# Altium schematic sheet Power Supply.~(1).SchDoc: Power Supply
size 431 x 279 mm; Date: Not shown in title block; ApprovedBy: Not shown in title block; CheckedBy: Not shown in title block; Author: Not shown in title block; CompanyName: Not shown in title block; Engineer: Not shown in title block; Organization: Not shown in title block; Address1: Not shown in title block; Address2: Not shown in title block; Address3: Not shown in title block; Address4: Not shown in title block; DocumentNumber: 3; Revision: Use project parameter SCH_Rev; SheetNumber: 3; SheetTotal: 9; PageSetup: Record=PageOptions|CenterHorizontal=True|CenterVertical=True|PrintScale=1.00|XCorrection=1.00|YCorrection=1.00|PrintKind=0|BorderSize=5000000|LeftOffset=0|BottomOffset=0|Orientation=2|PaperLength=1000|PaperWidth=1000|Scale=100|PaperSource=15|PrintQuality=600|MediaType=1|DitherType=10|PaperKind=Letter|PrintScaleMode=1
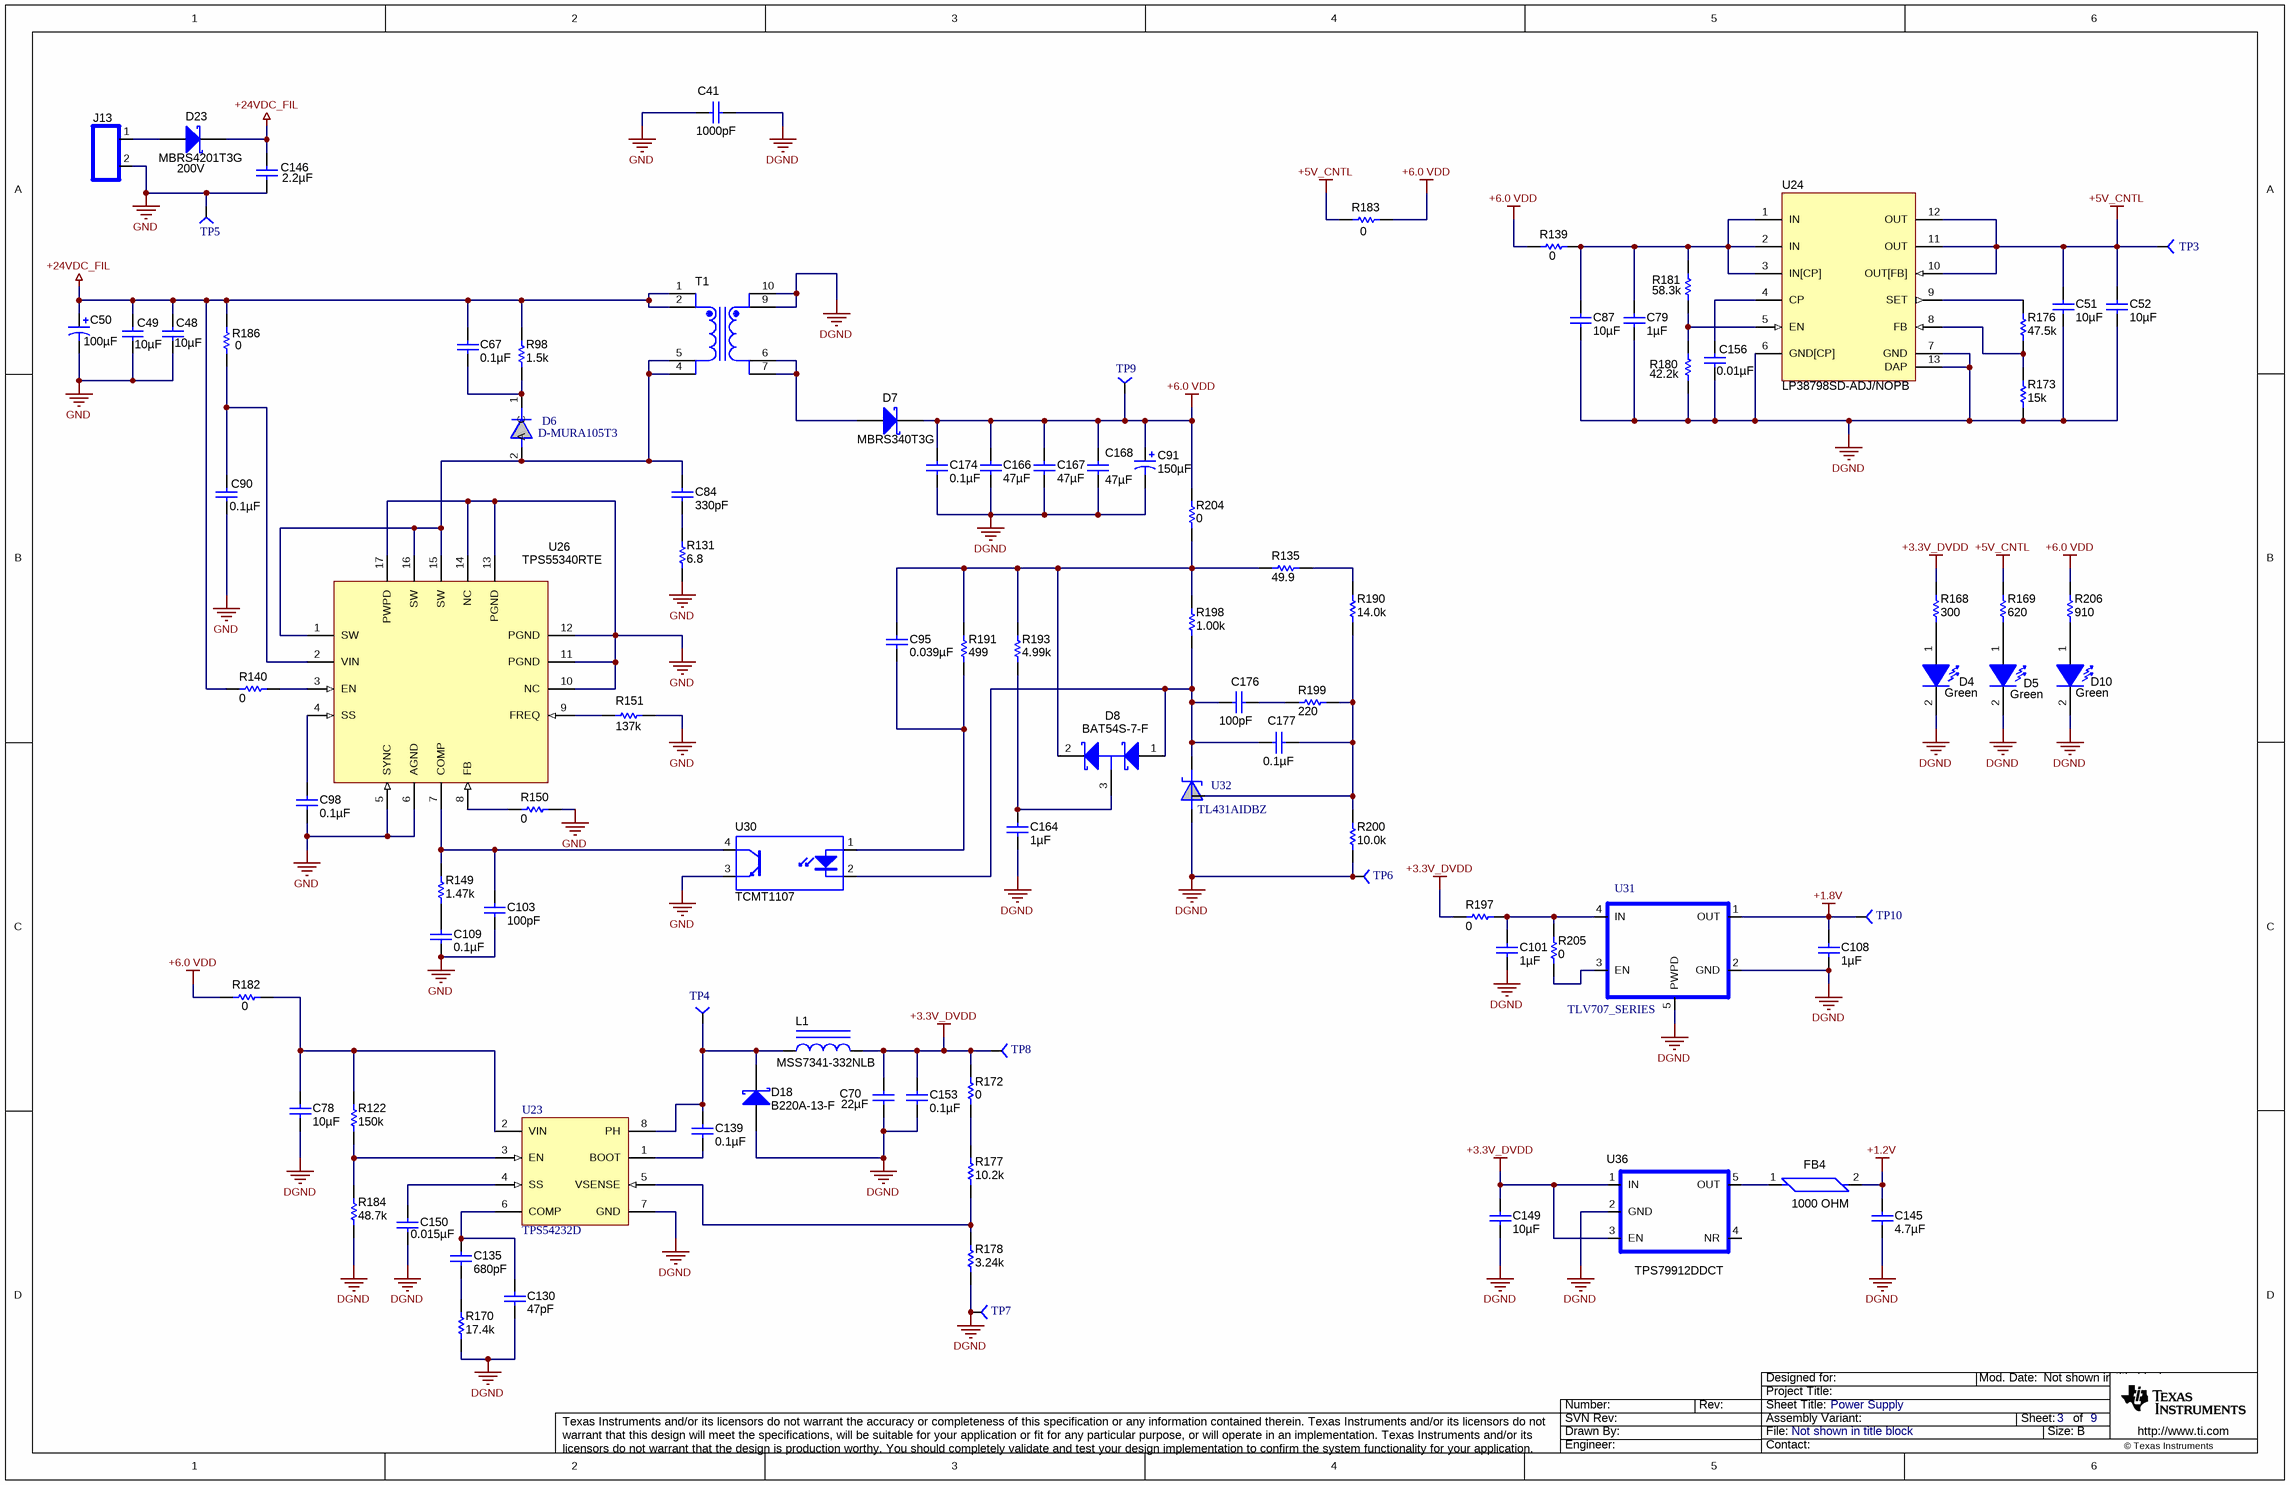
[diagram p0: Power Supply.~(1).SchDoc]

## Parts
C41  value 1000pF  [1206]
C48  ValueDisplayed: 10µF  [1210]  (hidden comment: GRM32ER71H106KA12L)
C49  ValueDisplayed: 10µF  [1210]  (hidden comment: GRM32ER71H106KA12L)
C50  ValueDisplayed: 100µF  [HE_800x1150]  (hidden comment: UHE1H101MPD)
C51  ValueDisplayed: 10µF  [1206]  (hidden comment: GRM31CR71C106KAC7L)
C52  ValueDisplayed: 10µF  [1206]  (hidden comment: GRM31CR71C106KAC7L)
C67  ValueDisplayed: 0.1µF  [0603]  (hidden comment: C0603C104K5RACTU)
C70  ValueDisplayed: 22µF  [1210]  (hidden comment: C3225X5R1A226M)
C78  ValueDisplayed: 10µF  [1206]  (hidden comment: GMK316AB7106KL)
C79  ValueDisplayed: 1µF  [1206]  (hidden comment: 12063C105KAT2A)
C84  ValueDisplayed: 330pF  [0603]  (hidden comment: 06035A331JAT2A)
C87  ValueDisplayed: 10µF  [1206]  (hidden comment: GRM31CR71C106KAC7L)
C90  ValueDisplayed: 0.1µF  [0603]  (hidden comment: C0603C104K5RACTU)
C91  ValueDisplayed: 150µF  [SM_RADIAL_6.3BMM]  (hidden comment: UUD1C151MCL1GS)
C95  ValueDisplayed: 0.039µF  [0603]  (hidden comment: GRM188R71H393KA61D)
C98  ValueDisplayed: 0.1µF  [0603]  (hidden comment: 06035C104KAT2A)
C101  ValueDisplayed: 1µF  [0603]  (hidden comment: GRM188R71A105KA61D)
C103  ValueDisplayed: 100pF  [0603]  (hidden comment: C1608C0G1H101J)
C108  ValueDisplayed: 1µF  [0603]  (hidden comment: GRM188R71A105KA61D)
C109  ValueDisplayed: 0.1µF  [0603]  (hidden comment: C0603C104K5RACTU)
C130  ValueDisplayed: 47pF  [0402]  (hidden comment: GRM1555C1E470JA01D)
C135  ValueDisplayed: 680pF  [0603]  (hidden comment: GRM1885C1E681JA01D)
C139  ValueDisplayed: 0.1µF  [0603]  (hidden comment: 0603YC104JAT2A)
C145  ValueDisplayed: 4.7µF  [0603]  (hidden comment: C0603C475K9PACTU)
C146  ValueDisplayed: 2.2µF  [1210]
C149  ValueDisplayed: 10µF  [1210]
C150  ValueDisplayed: 0.015µF  [0603]  (hidden comment: GRM188R71C153KA01D)
C153  ValueDisplayed: 0.1µF  [0603]  (hidden comment: C0603X104K8RACTU)
C156  ValueDisplayed: 0.01µF  [0805_HV]  (hidden comment: 08055C103KAT2A)
C164  ValueDisplayed: 1µF  [0603]  (hidden comment: C0603C105K4PACTU)
C166  ValueDisplayed: 47µF  [1210]  (hidden comment: GRM32ER61A476KE20L)
C167  ValueDisplayed: 47µF  [1210]  (hidden comment: GRM32ER61A476KE20L)
C168  ValueDisplayed: 47µF  [1210]  (hidden comment: GRM32ER61A476KE20L)
C174  ValueDisplayed: 0.1µF  [0603]  (hidden comment: C0603X104K8RACTU)
C176  ValueDisplayed: 100pF  [0603]  (hidden comment: C1608C0G1H101J)
C177  ValueDisplayed: 0.1µF  [0603]  (hidden comment: C0603C104K5RACTU)
D4  value Green  [LED_0603]  (hidden comment: LG L29K-G2J1-24-Z)
D5  value Green  [LED_0603]  (hidden comment: LG L29K-G2J1-24-Z)
D6  D-MURA105T3  [403D]
D7  MBRS340T3G  [SMC]
D8  BAT54S-7-F  [SOT-23]
D10  value Green  [LED_0603]  (hidden comment: LG L29K-G2J1-24-Z)
D18  B220A-13-F  [SMA]
D23  value 200V  [SMC]  (hidden comment: MBRS4201T3G)
FB4  value 1000 OHM  [FB0603]
J13  TBLK_15A_2X5.1MM  [TB_2X5.1MM]  (value not drawn)
L1  MSS7341-332NLB  [MSS7341]
R98  value 1.5k  [1206]  (hidden comment: CRCW12061K50JNEA)
R122  value 150k  [0603]  (hidden comment: RC0603FR-07150KL)
R131  value 6.8  [1206]  (hidden comment: CRCW12066R80JNEA)
R135  value 49.9  [0603]  (hidden comment: CRCW060349R9FKEA)
R139  value 0  [0603]  (hidden comment: CRCW06030000Z0EA)
R140  value 0  [0603]  (hidden comment: CRCW06030000Z0EA)
R149  value 1.47k  [0603]  (hidden comment: RC0603FR-071K47L)
R150  value 0  [0603]  (hidden comment: CRCW06030000Z0EA)
R151  value 137k  [0603]  (hidden comment: CRCW0603137KFKEA)
R168  value 300  [0603]  (hidden comment: CRCW0603300RJNEA)
R169  value 620  [0603]  (hidden comment: RC0603FR-07620RL)
R170  value 17.4k  [0603]  (hidden comment: CRCW060317K4FKEA)
R172  value 0  [0603]  (hidden comment: RC0603JR-070RL)
R173  value 15k  [0603]  (hidden comment: CRCW060315K0JNEA)
R176  value 47.5k  [0603]  (hidden comment: CRCW060347K5FKEA)
R177  value 10.2k  [0603]  (hidden comment: CRCW060310K2FKEA)
R178  value 3.24k  [0603]  (hidden comment: CRCW06033K24FKEA)
R180  value 42.2k  [0603]  (hidden comment: RC0603FR-0742K2L)
R181  value 58.3k  [0603]  (hidden comment: RT0603BRD0758K3L)
R182  value 0  [1206]  (hidden comment: CRCW12060000Z0EA)
R183  value 0  [1206]  (hidden comment: CRCW12060000Z0EA)
R184  value 48.7k  [0603]  (hidden comment: CRCW060348K7FKEA)
R186  value 0  [0603]  (hidden comment: CRCW06030000Z0EA)
R190  value 14.0k  [0603]  (hidden comment: CRCW060314K0FKEA)
R191  value 499  [0603]  (hidden comment: CRCW0603499RFKEA)
R193  value 4.99k  [0603]  (hidden comment: CRCW06034K99FKEA)
R197  value 0  [0603]  (hidden comment: RC0603JR-070RL)
R198  value 1.00k  [0603]  (hidden comment: CRCW06031K00FKEA)
R199  value 220  [0603]  (hidden comment: RC0603FR-07220RL)
R200  value 10.0k  [0603]  (hidden comment: CRCW060310K0FKEA)
R204  value 0  [0603]  (hidden comment: CRCW06030000Z0EA)
R205  value 0  [0603]  (hidden comment: RC0603JR-070RL)
R206  value 910  [0603]  (hidden comment: RG1608P-911-B-T5)
T1  (no value)  [XFARMER]
TP3  TP-SMALL  [TP-SMALL]  (value not drawn)
TP4  TP-SMALL  [TP-SMALL]  (value not drawn)
TP5  TP-SMALL  [TP-SMALL]  (value not drawn)
TP6  TP-SMALL  [TP-SMALL]  (value not drawn)
TP7  TP-SMALL  [TP-SMALL]  (value not drawn)
TP8  TP-SMALL  [TP-SMALL]  (value not drawn)
TP9  TP-SMALL  [TP-SMALL]  (value not drawn)
TP10  TP-SMALL  [TP-SMALL]  (value not drawn)
U23  TPS54232D  [D0008A_N]
U24  LP38798SD-ADJ/NOPB  [DNT0012B]
U26  TPS55340RTE  [RTE0016C]
U30  TCMT1107  [SOP-4]
U31  TLV707_SERIES  [UDFN-4P-1X1_MM]
U32  TL431AIDBZ  [SOT-23]
U36  TPS79912DDCT  [DDC0005A_N]

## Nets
+1.2V: C145.1 FB4.2
+1.8V: C108.1 TP10.1 U31.1(OUT)
+3.3V_DVDD: C70.1 C149.1 C153.1 L1.2 R168.2 R172.2 R197.2 TP8.1 U36.1(IN) U36.3(EN)
+5V_CNTL: C51.1 C52.1 R169.2 R183.1 TP3.1 U24.10(OUT[FB]) U24.11(OUT) U24.12(OUT)
+6.0 VDD: C91.1(+) C166.1 C167.1 C168.1 C174.1 D7.1(K) R139.2 R182.1 R183.2 R204.2 R206.2 TP9.1
+24VDC_FIL: C48.1 C49.1 C50.1(+) C67.1 C146.1 D23.1(K) R98.2 R140.2 R186.2 T1.1 T1.2
DGND: C41.2 C51.2 C52.2 C70.2 C78.2 C79.2 C87.2 C91.2(-) C101.2 C108.2 C130.2 C145.2 C149.2 C150.2 C153.2 C156.2 C164.2 C166.2 C167.2 C168.2 C174.2 D4.2(K) D5.2(K) D10.2(K) D18.2(A) R170.1 R173.1 R178.1 R180.1 R184.1 R200.1 T1.9 T1.10 TP6.1 TP7.1 U23.7(GND) U24.6(GND[CP]) U24.7(GND) U24.13(DAP) U31.2(GND) U31.5(PWPD) U32.3(A) U36.2(GND)
GND: C41.1 C48.2 C49.2 C50.2(-) C90.2 C98.2 C103.2 C109.2 C146.2 J13.2 R131.1 R150.2 R151.2 TP5.1 U26.5(SYNC) U26.6(AGND) U26.10(NC) U26.11(PGND) U26.12(PGND) U26.13(PGND) U26.14(NC) U26.17(PWPD) U30.3(E)
NetC67_2: C67.2 D6.1(C) R98.1
NetC78_1: C78.1 R122.2 R182.2 U23.2(VIN)
NetC79_1: C79.1 C87.1 R139.1 R181.2 U24.1(IN) U24.2(IN) U24.3(IN[CP])
NetC84_1: C84.1 D6.2(A) T1.4 T1.5 U26.1(SW) U26.15(SW) U26.16(SW)
NetC84_2: C84.2 R131.2
NetC90_1: C90.1 R186.1 U26.2(VIN)
NetC95_1: C95.1 D8.2(K) R135.1 R191.2 R193.2 R198.2 R204.1
NetC95_2: C95.2 R191.1 U30.1(A)
NetC98_1: C98.1 U26.4(SS)
NetC101_1: C101.1 R197.1 R205.2 U31.4(IN)
NetC103_1: C103.1 R149.2 U26.7(COMP) U30.4(C)
NetC109_1: C109.1 R149.1
NetC130_1: C130.1 C135.1 U23.6(COMP)
NetC135_2: C135.2 R170.2
NetC139_1: C139.1 D18.1(K) L1.1 TP4.1 U23.8(PH)
NetC139_2: C139.2 U23.1(BOOT)
NetC150_1: C150.1 U23.4(SS)
NetC156_1: C156.1 U24.4(CP)
NetC164_1: C164.1 D8.3(C) R193.1
NetC176_1: C176.1 R199.1
NetC176_2: C176.2 C177.1 D8.1(A) R198.1 U30.2(K) U32.1(C)
NetC177_2: C177.2 R190.1 R199.2 R200.2 U32.2(REF)
NetD4_1: D4.1(A) R168.1
NetD5_1: D5.1(A) R169.1
NetD7_2: D7.2(A) T1.6 T1.7
NetD10_1: D10.1(A) R206.1
NetD23_2: D23.2(A) J13.1
NetFB4_1: FB4.1 U36.5(OUT)
NetR122_1: R122.1 R184.2 U23.3(EN)
NetR135_2: R135.2 R190.2
NetR140_1: R140.1 U26.3(EN)
NetR150_1: R150.1 U26.8(FB)
NetR151_1: R151.1 U26.9(FREQ)
NetR172_1: R172.1 R177.2
NetR173_2: R173.2 R176.1 U24.8(FB)
NetR176_2: R176.2 U24.9(SET)
NetR177_1: R177.1 R178.2 U23.5(VSENSE)
NetR180_2: R180.2 R181.1 U24.5(EN)
NetR205_1: R205.1 U31.3(EN)

Not connected (* = marked no-connect by the designer): U36 4(NR)

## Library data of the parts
C41 = 202R18W102KV4E: CAP, CERM, 1000pF, 2KV 10% X7R 1206; Manufacturer: Johanson Dielectrics Inc; Polarized: N; CompType: Capacitor; Cap_F: 0.000000001; Tolerance_%: 0
C48 C49 = GRM32ER71H106KA12L: CAP, CERM, 10uF, 50V, +/-10%, X7R, 1210; Manufacturer: MuRata; Polarized: N; CompType: Capacitor; U/M: EA; Cap_F: 0.00001; Tolerance_%: 10; Value1: Unknown; VDC_V: 50; TaMin_C: -55; TaMax_C: 125
C50 = UHE1H101MPD: CAP, AL, 100uF, 50V, +/-20%, 0.17 ohm, TH; Manufacturer: Nichicon; Polarized: Y; CompType: Capacitor; U/M: EA; Cap_F: 0.0001; Tolerance_%: 20; VDC_V: 50; ESR_Ohm: 0.17; IRMS_A: 0.555; TaMin_C: -40; TaMax_C: 105; Cap_Case: 8x11.5
C51 C52 C87 = GRM31CR71C106KAC7L: CAP, CERM, 10uF, 16V, +/-10%, X7R, 1206; Manufacturer: MuRata; Polarized: N; CompType: Capacitor; U/M: EA; Cap_F: 0.00001; Tolerance_%: 10; Value1: Unknown; VDC_V: 16; TaMin_C: -55; TaMax_C: 125
C67 C90 C109 C177 = C0603C104K5RACTU: CAP, CERM, 0.1uF, 50V, +/-10%, X7R, 0603; Manufacturer: Kemet; Polarized: N; CompType: Capacitor; U/M: EA; Cap_F: 0.0000001; Tolerance_%: 10; Value1: Unknown; VDC_V: 50; TaMin_C: -55; TaMax_C: 125
C70 = C3225X5R1A226M: CAP, CERM, 22uF, 10V, +/-20%, X5R, 1210; Manufacturer: TDK; Polarized: N; CompType: Capacitor; U/M: EA; Cap_F: 0.000022; Tolerance_%: 20; ESR_Ohm: 0.002; Value1: 0.002 ohm; VDC_V: 10; IRMS_A: 3.2; TaMin_C: -55; TaMax_C: 85
C78 = GMK316AB7106KL: CAP, CERM, 10uF, 35V, +/-10%, X7R, 1206; Manufacturer: Taiyo Yuden; Polarized: N; CompType: Capacitor; U/M: EA; Cap_F: 0.00001; Tolerance_%: 10; Value1: Unknown; VDC_V: 35; TaMin_C: -55; TaMax_C: 125
C79 = 12063C105KAT2A: CAP, CERM, 1uF, 25V, +/-10%, X7R, 1206; Manufacturer: AVX; Polarized: N; CompType: Capacitor; U/M: EA; Cap_F: 0.000001; Tolerance_%: 10; ESR_Ohm: 0.013; Value1: 0.013 ohm; VDC_V: 25; TaMin_C: -55; TaMax_C: 125
C84 = 06035A331JAT2A: CAP, CERM, 330pF, 50V, +/-5%, C0G/NP0, 0603; Manufacturer: AVX; Polarized: N; CompType: Capacitor; U/M: EA; Cap_F: 0.00000000033; Tolerance_%: 5; ESR_Ohm: 0.071; Value1: 0.071 ohm; VDC_V: 50; TaMin_C: -55; TaMax_C: 125
C91 = UUD1C151MCL1GS: CAP, AL, 150uF, 16V, +/-20%, 0.34 ohm, SMD; Manufacturer: Nichicon; Polarized: Y; CompType: Capacitor; U/M: EA; Cap_F: 0.00015; Tolerance_%: 20; VDC_V: 16; ESR_Ohm: 0.34; IRMS_A: 0.28; TaMin_C: -55; TaMax_C: 105; Cap_Case: 6.3x7.7
C95 = GRM188R71H393KA61D: CAP, CERM, 0.039uF, 50V, +/-10%, X7R, 0603; Manufacturer: MuRata; Polarized: N; CompType: Capacitor; U/M: EA; Cap_F: 0.000000039; Tolerance_%: 10; Value1: Unknown; VDC_V: 50; TaMin_C: -55; TaMax_C: 125
C98 = 06035C104KAT2A: CAP, CERM, 0.1uF, 50V, +/-10%, X7R, 0603; Manufacturer: AVX; Polarized: N; CompType: Capacitor; U/M: EA; Cap_F: 0.0000001; Tolerance_%: 10; Value1: Unknown; VDC_V: 50; TaMin_C: -55; TaMax_C: 125
C101 C108 = GRM188R71A105KA61D: CAP, CERM, 1uF, 10V, +/-10%, X7R, 0603; Manufacturer: MuRata; Polarized: N; CompType: Capacitor; U/M: EA; Cap_F: 0.000001; Tolerance_%: 10; ESR_Ohm: 0.011; Value1: 0.011 ohm; TaMin_C: -55; TaMax_C: 125
C103 C176 = C1608C0G1H101J: CAP, CERM, 100pF, 50V, +/-5%, C0G/NP0, 0603; Manufacturer: TDK; Polarized: N; CompType: Capacitor; U/M: EA; Cap_F: 0.0000000001; Tolerance_%: 5; ESR_Ohm: 0.1679; Value1: 0.1679 ohm; VDC_V: 50; TaMin_C: -55; TaMax_C: 125
C130 = GRM1555C1E470JA01D: CAP, CERM, 47pF, 25V, +/-5%, C0G/NP0, 0402; Manufacturer: MuRata; Polarized: N; CompType: Capacitor; U/M: EA; Cap_F: 0.000000000047; Tolerance_%: 5; Value1: Unknown; VDC_V: 25; TaMin_C: -55; TaMax_C: 125
C135 = GRM1885C1E681JA01D: CAP, CERM, 680pF, 25V, +/-5%, C0G/NP0, 0603; Manufacturer: MuRata; Polarized: N; CompType: Capacitor; U/M: EA; Cap_F: 0.00000000068; Tolerance_%: 5; Value1: Unknown; VDC_V: 25; TaMin_C: -55; TaMax_C: 125
C139 = 0603YC104JAT2A: CAP, CERM, 0.1uF, 16V, +/-5%, X7R, 0603; Manufacturer: AVX; Polarized: N; CompType: Capacitor; U/M: EA; Cap_F: 0.0000001; Tolerance_%: 5; ESR_Ohm: 0.039; Value1: 0.039 ohm; VDC_V: 16; TaMin_C: -55; TaMax_C: 125
C145 = C0603C475K9PACTU: CAP, CERM, 4.7uF, 6.3V, +/-10%, X5R, 0603; Manufacturer: Kemet; Polarized: N; CompType: Capacitor; U/M: EA; Cap_F: 0.0000047; Tolerance_%: 10; ESR_Ohm: 0.006; Value1: 0.006 ohm; VDC_V: 6.3; IRMS_A: 7.24; TaMin_C: -55; TaMax_C: 85
C146 = GRM32ER72A225KA35L: CAP, CERM, 2.2uF, 100V, +/-10%, X7R, 1210; Manufacturer: MuRata; Polarized: N; CompType: Capacitor; U/M: EA; Cap_F: 0.0000022; Tolerance_%: 10; ESR_Ohm: 0.007; Value1: 0.007 ohm; VDC_V: 100; IRMS_A: 4.4; TaMin_C: -55; TaMax_C: 125
C149 = GMK325AB7106MM-T: CAP, CERM, 10uF, 35V, +/-20%, X7R, 1210; Manufacturer: Taiyo Yuden; Polarized: N; CompType: Capacitor; U/M: EA; Cap_F: 0.00001; Tolerance_%: 20; Value1: Unknown; VDC_V: 35; TaMin_C: -55; TaMax_C: 125
C150 = GRM188R71C153KA01D: CAP, CERM, 0.015uF, 16V, +/-10%, X7R, 0603; Manufacturer: MuRata; Polarized: N; CompType: Capacitor; U/M: EA; Cap_F: 0.000000015; Tolerance_%: 10; Value1: Unknown; VDC_V: 16; TaMin_C: -55; TaMax_C: 125
C153 C174 = C0603X104K8RACTU: CAP, CERM, 0.1uF, 10V, +/-10%, X7R, 0603; Manufacturer: Kemet; Polarized: N; CompType: Capacitor; U/M: EA; Cap_F: 0.0000001; Tolerance_%: 10; Value1: Unknown; TaMin_C: -55; TaMax_C: 125
C156 = 08055C103KAT2A: CAP, CERM, 0.01uF, 50V, +/-10%, X7R, 0805; Manufacturer: AVX; Polarized: N; CompType: Capacitor; U/M: EA; Cap_F: 0.00000001; Tolerance_%: 10; ESR_Ohm: 0.078; Value1: 0.078 ohm; VDC_V: 50; TaMin_C: -55; TaMax_C: 125; Cap_Case: 0805
C164 = C0603C105K4PACTU: CAP, CERM, 1uF, 16V, +/-10%, X5R, 0603; Manufacturer: Kemet; Polarized: N; CompType: Capacitor; U/M: EA; Cap_F: 0.000001; Tolerance_%: 10; Value1: Unknown; VDC_V: 16; TaMin_C: -55; TaMax_C: 85
C166-C168 = GRM32ER61A476KE20L: CAP, CERM, 47uF, 10V, +/-10%, X5R, 1210; Manufacturer: MuRata; Polarized: N; CompType: Capacitor; U/M: EA; Cap_F: 0.000047; Tolerance_%: 10; ESR_Ohm: 0.001; Value1: 0.001 ohm; TaMin_C: -55; TaMax_C: 85
D4 D5 D10 = LG M47K-G1J2-24-Z: LED SMARTLED GREEN 570NM 0603; Manufacturer: OSRAM Opto Semiconductors Inc; Vf_V: 1.7V; Io_A: 0.002; RJC_CperW: 530; Tjmax_C: 100; Value1: W; U/M: EA
D6 = D-MURA105T3: Rectifier, Ultrafast Power, 50V 1A; Manufacturer: On Semi; Area: 4088
D7 = MBRS340T3G: Diode, Schottky, 40V, 3A, SMC; Manufacturer: ON Semiconductor; U/M: EA; Vf_V: 0.525; Value2: 0.525V; Io_A: 3; Vr_V: 40; TJmax_C: 125; RJC_CperW: 11
D8 = BAT54S-7-F: Diode, Schottky, 30V, 0.2A, SOT-23; Manufacturer: Diodes Inc.; U/M: EA; Vf_V: 0.65; Value2: 0.65V; Io_A: 0.2; Vr_V: 30; TJmax_C: 125
D18 = B220A-13-F: Diode, Schottky, 20V, 2A, SMA; Manufacturer: Diodes Inc.; U/M: EA; Vf_V: 0.5; Value2: 0.5V; Io_A: 2; Vr_V: 20; TJmax_C: 150
D23 = MBRS4201T3G: Diode, Schottky, 200V, 4A, SMC; Manufacturer: ON Semiconductor; Io_A: 4
FB4 = MMZ1608B102C: FERRITE CHIP 1000 OHM 300MA 0603; Manufacturer: TDK Corporation; CompType: Ferrite Bead
J13 = TBLK_15A_2X5.1MM: Terminal Block, 2-pin, 15-A, 5.1mm; Manufacturer: OST; PartNumber: ED120/2DS; area: 141600; Value: ED120/2DS
L1 = MSS7341-332NLB: Inductor, Shielded Drum Core, Ferrite, 3.3uH, 3.72A, 0.02 ohm, SMD; Manufacturer: Coilcraft; Ind_H: 3.3E-6; ValueDisplayed: 3.3µH; Imax_A: 3.72; Irms: 5A @ 40C rise; Isat: 3.72A @ 30% inductance drop; DCR_ohm: 0.02; U/M: EA
R98 = CRCW12061K50JNEA: RES, 1.5k ohm, 5%, 0.25W, 1206; Manufacturer: Vishay-Dale; CompType: Resistor; Res_ohm: 1500; Value_Code: 1k50; Tolerance_%: 5; Power_W: 0.25; VDC_V: 200; TempCo: 200 ppm/C; EIA_Code: E24; U/M: EA
R122 = RC0603FR-07150KL: RES, 150k ohm, 1%, 0.1W, 0603; Manufacturer: Yageo America; CompType: Resistor; Res_ohm: 150000; Tolerance_%: 1; Power_W: 0.1; VDC_V: 150; TempCo: 200 ppm/C; EIA_Code: E96; U/M: EA
R131 = CRCW12066R80JNEA: RES, 6.8 ohm, 5%, 0.25W, 1206; Manufacturer: Vishay-Dale; CompType: Resistor; Value_Code: 6R80; Tolerance_%: 5; Power_W: 0.25; VDC_V: 200; TempCo: 200 ppm/C; EIA_Code: E24; U/M: EA
R135 = CRCW060349R9FKEA: RES, 49.9 ohm, 1%, 0.1W, 0603; Manufacturer: Vishay-Dale; CompType: Resistor; Value_Code: 49R9; Tolerance_%: 1; Power_W: 0.1; VDC_V: 75; TempCo: 100 ppm/C; EIA_Code: E96; U/M: EA
R139 R140 R150 R186 R204 = CRCW06030000Z0EA: RES, 0 ohm, 5%, 0.1W, 0603; Manufacturer: Vishay-Dale; CompType: Resistor; Value_Code: 0000; Tolerance_%: 5; Power_W: 0.1; VDC_V: 75; TempCo: 200 ppm/C; EIA_Code: E24; U/M: EA
R149 = RC0603FR-071K47L: RES, 1.47k ohm, 1%, 0.1W, 0603; Manufacturer: Yageo America; CompType: Resistor; Res_ohm: 1470; Value_Code: 1k47; Tolerance_%: 1; Power_W: 0.1; VDC_V: 150; TempCo: 200 ppm/C; EIA_Code: E96; U/M: EA
R151 = CRCW0603137KFKEA: RES, 137k ohm, 1%, 0.1W, 0603; Manufacturer: Vishay-Dale; CompType: Resistor; Res_ohm: 137000; Tolerance_%: 1; Power_W: 0.1; VDC_V: 75; TempCo: 100 ppm/C; EIA_Code: E96; U/M: EA
R168 = CRCW0603300RJNEA: RES, 300 ohm, 5%, 0.1W, 0603; Manufacturer: Vishay-Dale; CompType: Resistor; Value_Code: 300R; Tolerance_%: 5; Power_W: 0.1; VDC_V: 75; TempCo: 200 ppm/C; EIA_Code: E24; U/M: EA
R169 = RC0603FR-07620RL: RES, 620 ohm, 1%, 0.1W, 0603; Manufacturer: Yageo America; CompType: Resistor; Value_Code: 620R; Tolerance_%: 1; Power_W: 0.1; VDC_V: 150; TempCo: 200 ppm/C; U/M: EA
R170 = CRCW060317K4FKEA: RES, 17.4k ohm, 1%, 0.1W, 0603; Manufacturer: Vishay-Dale; CompType: Resistor; Res_ohm: 17400; Value_Code: 17k4; Tolerance_%: 1; Power_W: 0.1; VDC_V: 75; TempCo: 100 ppm/C; EIA_Code: E96; U/M: EA
R172 R197 R205 = RC0603JR-070RL: RES, 0 ohm, 5%, 0.1W, 0603; Manufacturer: Yageo America; CompType: Resistor; Value_Code: 0000; Tolerance_%: 5; Power_W: 0.1; VDC_V: 50; TempCo: 200 ppm/C; EIA_Code: E24; U/M: EA
R173 = CRCW060315K0JNEA: RES, 15k ohm, 5%, 0.1W, 0603; Manufacturer: Vishay-Dale; CompType: Resistor; Res_ohm: 15000; Value_Code: 15k0; Tolerance_%: 5; Power_W: 0.1; VDC_V: 75; TempCo: 200 ppm/C; EIA_Code: E24; U/M: EA
R176 = CRCW060347K5FKEA: RES, 47.5k ohm, 1%, 0.1W, 0603; Manufacturer: Vishay-Dale; CompType: Resistor; Res_ohm: 47500; Value_Code: 47k5; Tolerance_%: 1; Power_W: 0.1; VDC_V: 75; TempCo: 100 ppm/C; EIA_Code: E96; U/M: EA
R177 = CRCW060310K2FKEA: RES, 10.2k ohm, 1%, 0.1W, 0603; Manufacturer: Vishay-Dale; CompType: Resistor; Res_ohm: 10200; Value_Code: 10k2; Tolerance_%: 1; Power_W: 0.1; VDC_V: 75; TempCo: 100 ppm/C; EIA_Code: E96; U/M: EA
R178 = CRCW06033K24FKEA: RES, 3.24k ohm, 1%, 0.1W, 0603; Manufacturer: Vishay-Dale; CompType: Resistor; Res_ohm: 3240; Value_Code: 3k24; Tolerance_%: 1; Power_W: 0.1; VDC_V: 75; TempCo: 100 ppm/C; EIA_Code: E96; U/M: EA
R180 = RC0603FR-0742K2L: RES, 42.2k ohm, 1%, 0.1W, 0603; Manufacturer: Yageo America; CompType: Resistor; Res_ohm: 42200; Value_Code: 42k2; Tolerance_%: 1; Power_W: 0.1; VDC_V: 150; TempCo: 200 ppm/C; EIA_Code: E96; U/M: EA
R181 = RT0603BRD0758K3L: RES, 58.3k ohm, 0.1%, 0.1W, 0603; Manufacturer: Yageo America; CompType: Resistor; Res_ohm: 58300; Value_Code: 58k3; Tolerance_%: 0.1; VDC_V: 75; TempCo: 25 ppm/C; EIA_Code: E192; U/M: EA
R182 R183 = CRCW12060000Z0EA: RES, 0 ohm, 5%, 0.25W, 1206; Manufacturer: Vishay-Dale; CompType: Resistor; Value_Code: 0000; Tolerance_%: 5; Power_W: 0.25; VDC_V: 200; TempCo: 200 ppm/C; EIA_Code: E24; U/M: EA
R184 = CRCW060348K7FKEA: RES, 48.7k ohm, 1%, 0.1W, 0603; Manufacturer: Vishay-Dale; CompType: Resistor; Res_ohm: 48700; Value_Code: 48k7; Tolerance_%: 1; Power_W: 0.1; VDC_V: 75; TempCo: 100 ppm/C; EIA_Code: E96; U/M: EA
R190 = CRCW060314K0FKEA: RES, 14.0k ohm, 1%, 0.1W, 0603; Manufacturer: Vishay-Dale; CompType: Resistor; Res_ohm: 14000; Value_Code: 14k0; Tolerance_%: 1; Power_W: 0.1; VDC_V: 75; TempCo: 100 ppm/C; EIA_Code: E96; U/M: EA
R191 = CRCW0603499RFKEA: RES, 499 ohm, 1%, 0.1W, 0603; Manufacturer: Vishay-Dale; CompType: Resistor; Value_Code: 499R; Tolerance_%: 1; Power_W: 0.1; VDC_V: 75; TempCo: 100 ppm/C; EIA_Code: E96; U/M: EA
R193 = CRCW06034K99FKEA: RES, 4.99k ohm, 1%, 0.1W, 0603; Manufacturer: Vishay-Dale; CompType: Resistor; Res_ohm: 4990; Value_Code: 4k99; Tolerance_%: 1; Power_W: 0.1; VDC_V: 75; TempCo: 100 ppm/C; EIA_Code: E96; U/M: EA
R198 = CRCW06031K00FKEA: RES, 1.00k ohm, 1%, 0.1W, 0603; Manufacturer: Vishay-Dale; CompType: Resistor; Res_ohm: 1000; Value_Code: 1k00; Tolerance_%: 1; Power_W: 0.1; VDC_V: 75; TempCo: 100 ppm/C; EIA_Code: E96; U/M: EA
R199 = RC0603FR-07220RL: RES, 220 ohm, 1%, 0.1W, 0603; Manufacturer: Yageo America; CompType: Resistor; Value_Code: 220R; Tolerance_%: 1; Power_W: 0.1; VDC_V: 150; TempCo: 200 ppm/C; U/M: EA
R200 = CRCW060310K0FKEA: RES, 10.0k ohm, 1%, 0.1W, 0603; Manufacturer: Vishay-Dale; CompType: Resistor; Res_ohm: 10000; Value_Code: 10k0; Tolerance_%: 1; Power_W: 0.1; VDC_V: 75; TempCo: 100 ppm/C; EIA_Code: E96; U/M: EA
R206 = RG1608P-911-B-T5: RES, 910 ohm, 0.1%, 0.1W, 0603; Manufacturer: Susumu Co Ltd; CompType: Resistor; Value_Code: 910R; Tolerance_%: 0.1; VDC_V: 75; TempCo: 25 ppm/C; U/M: EA
T1 = Transformer: SymbolCreator: a0411947; DCR_Ohm: 0.11; Value: 12uH; LeakageL: 0.130uH; U/M: EA
TP3-TP10 = TP-SMALL: Test Point, 0.020 Hole; Manufacturer: STD; Value: STD
U23 = TPS54232D: Buck Step Down Regulator with 3.5 to 28 V Input and 0.8 to 25 V Output, -40 to 150 degC, 8-Pin SOIC (D), Green (RoHS & no Sb/Br); Manufacturer: Texas Instruments; Alternate Manufacturer: None; Alternate PartNumber: Equivalent; Duty Cycle(Max)(%): 90; Iout(Max)(A): 2; Iq(Typ)(mA): 0.11; Rating: Catalog; Regulated Outputs(#): 1; SubFamily: Step-Down Regulator; Switch Current Limit(Typ)(A): 2.3; Vin(Max)(V): 28; Vin(Min)(V): 3.5; Vout(Max)(V): 25; Vout(Min)(V): 0.8
U24 = LP38798SD-ADJ/NOPB: Ultra Low Noise, 800 mA Linear Voltage Regulator for RF/Analog Circuits, DNT0012B; Alternate Manufacturer: None; Manufacturer: Texas Instruments; SymbolCreator: a0799628; CompType: IC; U/M: EA
U26 = TPS55340RTE: Integrated 5-A 40-V Wide Input Range Boost/SEPIC/Flyback DC-DC Regulator, RTE0016C; Alternate Manufacturer: None; Manufacturer: Texas Instruments; SymbolCreator: a0412235; CompType: IC; U/M: EA
U30 = TCMT1107: Optocoupler, 3.75kV RMS, SMT; Manufacturer: Vishay-Semiconductor; U/M: EA
U31 = TLV707_SERIES: IC, 150mA, Low IQ, LDO Regulator; PartNumber: TLV707xxx; Manufacturer: TI; Alternate Manufacturer: None; Area: 2.25 mm; Value: TLV707xxx
U32 = TL431AIDBZ: IC, Precision Adjustable Shunt Regulator; Manufacturer: TI; Alternate Manufacturer: None; Area: 16384; Value: TL431DBZ
U36 = TPS799XXDDC: IC, Ultra-low Noise, High PSRR 200 mA, LDO, 1.2V 0.2A 5SOT; Manufacturer: TI; Alternate Manufacturer: None; Area: 23200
